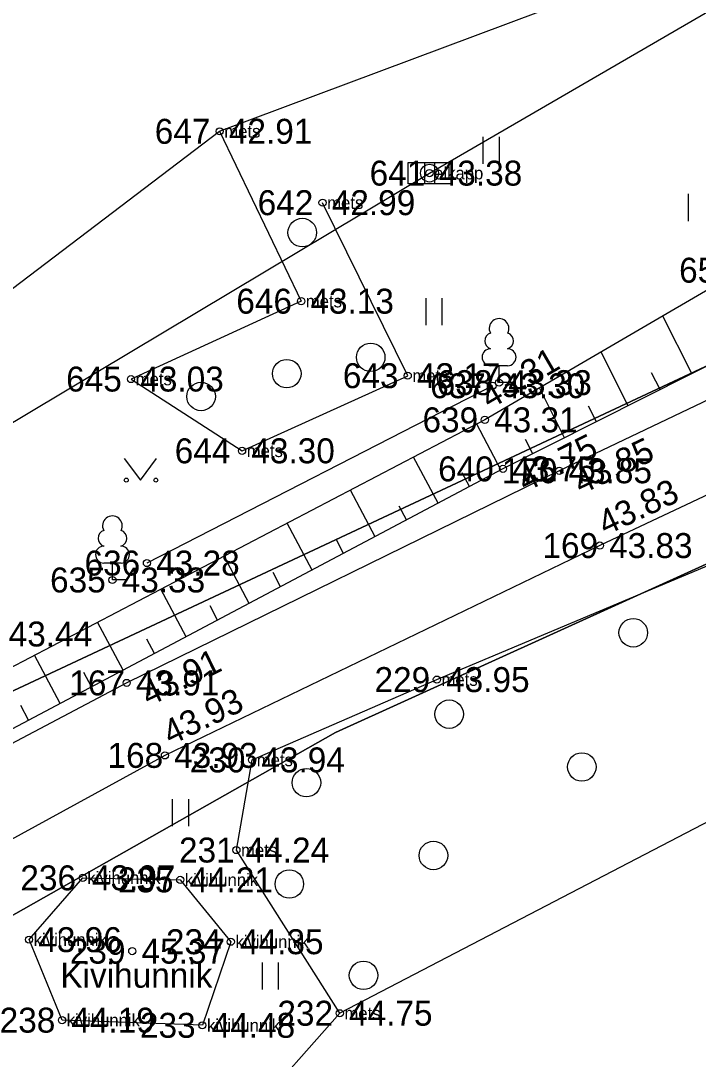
# Model space of a CAD drawing. Extents: x 505800 to 507326, y 6540058 to 6542128.
# Drawn here: x 506404.99 to 506423.99, y 6540355.67 to 6540384.81 of the extents above; entities that cross this region are included whole.
import ezdxf

# ---------------------------------------------------------------- set-up
doc = ezdxf.new("R2010")
doc.units = 0
for name, color, linetype in [('ELRAJATISMP', 7, 'Continuous'), ('HALJASTUS', 7, 'Continuous'), ('KORGUS-EH2000', 7, 'Continuous'), ('MAAMUDEL', 7, 'Continuous'), ('MOOTKORG-EH2000', 7, 'Continuous'), ('MOOTMPUNKT', 7, 'Continuous'), ('MOOTNR', 7, 'Continuous'), ('MOOTPIIR', 7, 'Continuous'), ('MPOHULIIN', 7, 'Continuous'), ('PIIR', 7, 'Continuous'), ('POST', 7, 'Continuous'), ('PUU', 7, 'Continuous'), ('RELJEEF', 7, 'Continuous'), ('TEE', 7, 'Continuous')]:
    doc.layers.add(name, color=color, linetype=linetype)

msp = doc.modelspace()

# ---------------------------------------------------------------- linework, layer by layer
at = {"layer": 'ELRAJATISMP'}
for p, q in [((506416.317, 6540380.834), (506416.317, 6540380.237)), ((506416.589, 6540380.834), (506416.589, 6540380.237))]:
    msp.add_line(p, q, dxfattribs=at)
msp.add_lwpolyline([(506415.856, 6540380.834), (506417.05, 6540380.834), (506417.05, 6540380.237), (506415.856, 6540380.237)], close=True, dxfattribs=at)
at = {"layer": 'HALJASTUS'}
for p, q in [((506417.949, 6540381.555), (506417.949, 6540380.794)), ((506418.404, 6540381.555), (506418.404, 6540380.794)), ((506423.714, 6540379.953), (506423.714, 6540379.192)), ((506416.348, 6540377.028), (506416.348, 6540376.267)), ((506416.803, 6540377.028), (506416.803, 6540376.267)), ((506418.22, 6540374.569), (506408.525, 6540369.592)), ((506407.884, 6540372.527), (506408.347, 6540371.92)), ((506408.347, 6540371.92), (506408.793, 6540372.527)), ((506409.232, 6540362.968), (506409.232, 6540362.207)), ((506409.687, 6540362.968), (506409.687, 6540362.207)), ((506411.754, 6540358.381), (506411.754, 6540357.62)), ((506412.209, 6540358.381), (506412.209, 6540357.62))]:
    msp.add_line(p, q, dxfattribs=at)
for points in [[(506413.936, 6540356.957), (506411.035, 6540361.537), (506411.476, 6540364.066), (506416.66, 6540366.321), (506428.112, 6540371.138), (506442.602, 6540377.508), (506445.225, 6540379.984), (506450.028, 6540381.664), (506456.825, 6540384.191), (506464.626, 6540386.148), (506480.51, 6540389.107), (506500.858, 6540392.966), (506504.844, 6540391.729), (506512.52, 6540393.396), (506515.37, 6540396.647), (506532.173, 6540402.941), (506544.149, 6540408.028), (506554.027, 6540411.411), (506558.081, 6540412.384), (506561.957, 6540411.866), (506565.619, 6540410.412), (506569.33, 6540407.843)], [(506410.565, 6540381.71), (506412.852, 6540376.942), (506408.079, 6540374.756), (506411.195, 6540372.742), (506415.842, 6540374.851), (506413.452, 6540379.706)], [(506410.08, 6540356.618), (506406.144, 6540356.763), (506405.218, 6540359.022), (506406.724, 6540360.757), (506409.459, 6540360.7), (506410.878, 6540358.964), (506410.08, 6540356.618)]]:
    msp.add_lwpolyline(points, dxfattribs=at)
for centre, radius in [((506412.882, 6540378.868), 0.4), ((506414.804, 6540375.366), 0.4), ((506412.448, 6540374.908), 0.4), ((506410.045, 6540374.267), 0.4), ((506407.946, 6540371.92), 0.055), ((506408.775, 6540371.92), 0.055), ((506422.169, 6540367.635), 0.4), ((506417.004, 6540365.351), 0.4), ((506420.727, 6540363.869), 0.4), ((506413, 6540363.428), 0.4), ((506416.564, 6540361.385), 0.4), ((506412.52, 6540360.584), 0.4), ((506414.602, 6540358.02), 0.4)]:
    msp.add_circle(centre, radius, dxfattribs=at)
at = {"layer": 'KORGUS-EH2000'}
for centre in [(506410.565, 6540381.71), (506416.453, 6540380.536), (506413.452, 6540379.706), (506412.852, 6540376.942), (506415.842, 6540374.851), (506408.079, 6540374.756), (506418.22, 6540374.569), (506418.406, 6540374.655), (506418.006, 6540373.612), (506411.195, 6540372.742), (506418.514, 6540372.235), (506420.092, 6540372.182), (506421.232, 6540370.083), (506408.525, 6540369.592), (506407.558, 6540369.117), (506407.957, 6540366.228), (506416.66, 6540366.321), (506409.03, 6540364.194), (506411.476, 6540364.066), (506411.035, 6540361.537), (506406.724, 6540360.757), (506409.459, 6540360.7), (506405.218, 6540359.022), (506410.878, 6540358.964), (506408.113, 6540358.7), (506406.144, 6540356.763), (506413.936, 6540356.957), (506410.08, 6540356.618)]:
    msp.add_circle(centre, 0.1, dxfattribs=at)
at = {"layer": 'MOOTMPUNKT'}
for centre in [(506410.565, 6540381.71), (506416.453, 6540380.536), (506413.452, 6540379.706), (506412.852, 6540376.942), (506415.842, 6540374.851), (506408.079, 6540374.756), (506418.22, 6540374.569), (506418.406, 6540374.655), (506418.006, 6540373.612), (506411.195, 6540372.742), (506418.514, 6540372.235), (506420.092, 6540372.182), (506421.232, 6540370.083), (506408.525, 6540369.592), (506407.558, 6540369.117), (506407.957, 6540366.228), (506416.66, 6540366.321), (506409.03, 6540364.194), (506411.476, 6540364.066), (506411.035, 6540361.537), (506406.724, 6540360.757), (506409.459, 6540360.7), (506405.218, 6540359.022), (506410.878, 6540358.964), (506408.113, 6540358.7), (506406.144, 6540356.763), (506413.936, 6540356.957), (506410.08, 6540356.618)]:
    msp.add_circle(centre, 0.1, dxfattribs=at)
at = {"layer": 'MOOTPIIR'}
for points in [[(506240.253, 6540270.959), (506245.955, 6540263.864), (506266.133, 6540270.794), (506275.983, 6540276.683), (506285.511, 6540285.657), (506298.843, 6540299.878), (506301.086, 6540304.525), (506297.722, 6540312.738), (506305.023, 6540318.445), (506309.38, 6540311.746), (506312.325, 6540315.185), (506338.029, 6540330.648), (506336.908, 6540340.183), (506347.357, 6540347.554), (506370.89, 6540361.705), (506382.389, 6540366.462), (506390.076, 6540368.866), (506400.572, 6540374.13), (506410.565, 6540381.71), (506441.143, 6540393.151), (506453.59, 6540403.335), (506461.402, 6540393.473), (506495.448, 6540402.285)], [(506495.183, 6540386.603), (506455.807, 6540378.751), (506413.936, 6540356.957), (506411.426, 6540354.112), (506402.307, 6540351.523), (506391.999, 6540341.498), (506380.901, 6540334.942), (506360.247, 6540322.568), (506353.013, 6540324.95), (506332.133, 6540309.036), (506315.598, 6540297.889), (506301.375, 6540281.904), (506292.827, 6540267.673), (506286.653, 6540264.508), (506248.469, 6540250.071)]]:
    msp.add_lwpolyline(points, dxfattribs=at)
at = {"layer": 'MPOHULIIN'}
for p, q in [((506416.453, 6540380.536), (506455.327, 6540403.116)), ((506372.493, 6540354.233), (506416.453, 6540380.536))]:
    msp.add_line(p, q, dxfattribs=at)
at = {"layer": 'PIIR'}
msp.add_lwpolyline([(506326.14, 6540370.11), (506324.04, 6540375.18), (506354.05, 6540393.57), (506395.54, 6540418.74), (506427.6, 6540438.79), (506429.21, 6540436.36), (506458.7, 6540391.28), (506340.34, 6540335.82)], close=True, dxfattribs=at)
for points in [[(506215.95, 6540254.34), (506268.55, 6540273.9), (506274.54, 6540277.85), (506304.35, 6540308.95), (506340.34, 6540335.82), (506458.7, 6540391.28), (506563.96, 6540420.02)], [(506497.85, 6540391.32), (506462.8, 6540384.69), (506453.27, 6540382.76), (506413.82, 6540364.84), (506374.55, 6540342.6), (506353.59, 6540332.53), (506318.07, 6540309.28), (506308, 6540301.95), (506281.65, 6540275.05), (506272.39, 6540267.75), (506224.13, 6540249.92)], [(506224.13, 6540249.92), (506272.39, 6540267.75), (506281.65, 6540275.05), (506308, 6540301.95), (506318.07, 6540309.28), (506353.59, 6540332.53), (506374.55, 6540342.6), (506413.82, 6540364.84), (506453.27, 6540382.76), (506462.8, 6540384.69), (506495.14, 6540337.45), (506342.85, 6540237.27), (506260.72, 6540195.9), (506215.68, 6540179.69)]]:
    msp.add_lwpolyline(points, dxfattribs=at)
at = {"layer": 'POST'}
msp.add_circle((506416.453, 6540380.536), 0.25, dxfattribs=at)
at = {"layer": 'PUU'}
for p, q in [((506418.646, 6540375.13), (506418.166, 6540375.13)), ((506418.406, 6540374.655), (506418.406, 6540375.13)), ((506418.786, 6540374.655), (506418.406, 6540374.655)), ((506407.798, 6540369.592), (506407.318, 6540369.592)), ((506407.558, 6540369.117), (506407.558, 6540369.592)), ((506407.938, 6540369.117), (506407.558, 6540369.117))]:
    msp.add_line(p, q, dxfattribs=at)
for centre, radius, start, end in [((506418.406, 6540376.175), 0.277, 332.5799, 207.4201), ((506418.236, 6540375.828), 0.233, 109.0217, 253.1415), ((506418.576, 6540375.828), 0.233, 286.8508, 70.9859), ((506418.168, 6540375.368), 0.238, 90.0016, 269.3953), ((506418.643, 6540375.368), 0.238, 270.6047, 89.9984), ((506407.558, 6540370.637), 0.277, 332.5799, 207.4201), ((506407.388, 6540370.289), 0.233, 109.0217, 253.1415), ((506407.728, 6540370.289), 0.233, 286.8508, 70.9859), ((506407.321, 6540369.829), 0.238, 90.0016, 269.3953), ((506407.796, 6540369.829), 0.238, 270.6047, 89.9984)]:
    msp.add_arc(centre, radius, start, end, dxfattribs=at)
at = {"layer": 'RELJEEF'}
for p, q in [((506423.815, 6540374.909), (506423, 6540376.525)), ((506422.03, 6540374.008), (506421.269, 6540375.515)), ((506422.923, 6540374.459), (506422.686, 6540374.927)), ((506420.244, 6540373.107), (506419.539, 6540374.506)), ((506421.137, 6540373.558), (506420.917, 6540373.994)), ((506418.459, 6540372.206), (506417.777, 6540373.492)), ((506419.351, 6540372.657), (506419.148, 6540373.06)), ((506416.692, 6540371.269), (506416.005, 6540372.565)), ((506417.575, 6540371.737), (506417.37, 6540372.125)), ((506414.925, 6540370.332), (506414.232, 6540371.639)), ((506415.808, 6540370.801), (506415.601, 6540371.191)), ((506413.157, 6540369.396), (506412.46, 6540370.712)), ((506414.041, 6540369.864), (506413.833, 6540370.258)), ((506411.39, 6540368.459), (506410.688, 6540369.785)), ((506412.274, 6540368.928), (506412.064, 6540369.324)), ((506409.623, 6540367.523), (506408.915, 6540368.859)), ((506410.507, 6540367.991), (506410.295, 6540368.39)), ((506407.856, 6540366.586), (506407.143, 6540367.932)), ((506408.739, 6540367.055), (506408.526, 6540367.457)), ((506406.089, 6540365.65), (506405.37, 6540367.005)), ((506406.972, 6540366.118), (506406.758, 6540366.523)), ((506405.205, 6540365.181), (506404.989, 6540365.59))]:
    msp.add_line(p, q, dxfattribs=at)
for points in [[(506556.207, 6540417.529), (506548.446, 6540415.756), (506537.177, 6540411.287), (506507.092, 6540401.356), (506493.818, 6540397.458), (506479.74, 6540393.488), (506463.711, 6540390.977), (506454.162, 6540389.588), (506445.961, 6540387.82), (506436.644, 6540384.929), (506428.217, 6540381.232), (506425.206, 6540377.812), (506418.006, 6540373.612), (506396.112, 6540362.165), (506387.822, 6540357.514)], [(506556.207, 6540417.529), (506549.32, 6540414.59), (506538.05, 6540410.165), (506520.494, 6540403.746), (506508.114, 6540399.97), (506494.198, 6540395.848), (506479.734, 6540392.802), (506464.199, 6540389.877), (506454.62, 6540387.729), (506446.277, 6540385.845), (506437.645, 6540382.533), (506432.878, 6540380.89), (506430.375, 6540378.218), (506418.514, 6540372.235), (506396.686, 6540360.667), (506388.239, 6540356.069)]]:
    msp.add_lwpolyline(points, dxfattribs=at)
at = {"layer": 'TEE'}
for points in [[(506478.706, 6540392.058), (506464.091, 6540389.4), (506454.678, 6540387.173), (506446.264, 6540384.451), (506435.18, 6540379.372), (506420.092, 6540372.182), (506407.957, 6540366.228), (506394.897, 6540359.329), (506383.759, 6540352.819), (506372.647, 6540346.37), (506363.224, 6540341.99), (506352.182, 6540336.393), (506347.174, 6540333.201), (506340.898, 6540329.111), (506329.323, 6540321.237)], [(506479.167, 6540389.797), (506464.651, 6540387.028), (506455.166, 6540384.708), (506447.071, 6540382.035), (506436.402, 6540377.232), (506421.232, 6540370.083), (506409.03, 6540364.194), (506396.144, 6540357.137), (506385.127, 6540350.766), (506373.749, 6540344.271), (506364.374, 6540339.718), (506353.506, 6540334.212), (506348.479, 6540331.101), (506342.338, 6540327.065), (506330.786, 6540319.25)]]:
    msp.add_lwpolyline(points, dxfattribs=at)

# ---------------------------------------------------------------- texts
at = {"layer": 'HALJASTUS'}
msp.add_text('Kivihunnik', height=0.7, dxfattribs=at).set_placement((506406.096, 6540357.674))
at = {"layer": 'KORGUS-EH2000'}
for s, p in [(' 42.91', (506410.565, 6540381.36)), (' 42.99', (506413.452, 6540379.356)), (' 43.03', (506408.079, 6540374.406)), (' 43.30', (506411.195, 6540372.392)), (' 43.95', (506416.66, 6540365.971)), (' 43.94', (506411.476, 6540363.717)), (' 44.24', (506411.035, 6540361.187)), (' 45.37', (506408.113, 6540358.35)), (' 44.19', (506406.144, 6540356.413)), (' 44.75', (506413.936, 6540356.607))]:
    msp.add_text(s, height=0.7, dxfattribs=at).set_placement(p)
for s, rotation, p in [(' 43.31', 30.255, (506417.918, 6540373.763)), (' 43.75', 26.7689, (506418.908, 6540371.454)), (' 43.85', 25.4801, (506420.469, 6540371.392)), (' 43.83', 25.2327, (506421.157, 6540370.242)), (' 43.91', 26.1323, (506408.343, 6540365.443)), (' 43.93', 25.7657, (506408.954, 6540364.351))]:
    msp.add_text(s, height=0.7, rotation=rotation, dxfattribs=at).set_placement(p)
at = {"layer": 'MAAMUDEL'}
for s, p in [(' mets', (506410.565, 6540381.535)), (' elkapp', (506416.453, 6540380.361)), (' mets', (506413.452, 6540379.531)), (' mets', (506412.852, 6540376.767)), (' mets', (506408.079, 6540374.581)), (' mets', (506415.842, 6540374.676)), (' mets', (506411.195, 6540372.567)), (' mets', (506416.66, 6540366.146)), (' mets', (506411.476, 6540363.891)), (' mets', (506411.035, 6540361.362)), (' kivihunnik', (506406.724, 6540360.582)), (' kivihunnik', (506409.459, 6540360.525)), (' kivihunnik', (506405.218, 6540358.847)), (' kivihunnik', (506410.878, 6540358.789)), (' mets', (506413.936, 6540356.782)), (' kivihunnik', (506406.144, 6540356.588)), (' kivihunnik', (506410.08, 6540356.443))]:
    msp.add_text(s, height=0.35, dxfattribs=at).set_placement(p)
at = {"layer": 'MOOTKORG-EH2000'}
for s, p in [(' 42.91', (506410.565, 6540381.36)), (' 43.38', (506416.453, 6540380.186)), (' 42.99', (506413.452, 6540379.356)), (' 43.13', (506412.852, 6540376.592)), (' 43.17', (506415.842, 6540374.501)), (' 43.03', (506408.079, 6540374.406)), (' 43.30', (506418.22, 6540374.219)), (' 43.33', (506418.406, 6540374.305)), (' 43.31', (506418.006, 6540373.262)), (' 43.30', (506411.195, 6540372.392)), (' 43.75', (506418.514, 6540371.885)), (' 43.85', (506420.092, 6540371.832)), (' 43.83', (506421.232, 6540369.733)), (' 43.28', (506408.525, 6540369.242)), (' 43.33', (506407.558, 6540368.767)), (' 43.44', (506404.386, 6540367.25)), (' 43.91', (506407.957, 6540365.878)), (' 43.95', (506416.66, 6540365.971)), (' 43.93', (506409.03, 6540363.844)), (' 43.94', (506411.476, 6540363.717)), (' 44.24', (506411.035, 6540361.187)), (' 43.97', (506406.724, 6540360.407)), (' 44.21', (506409.459, 6540360.35)), (' 43.96', (506405.218, 6540358.672)), (' 44.35', (506410.878, 6540358.614)), (' 45.37', (506408.113, 6540358.35)), (' 44.19', (506406.144, 6540356.413)), (' 44.75', (506413.936, 6540356.607)), (' 44.48', (506410.08, 6540356.268))]:
    msp.add_text(s, height=0.7, dxfattribs=at).set_placement(p)
at = {"layer": 'MOOTNR'}
for s, p in [('647 ', (506408.745, 6540381.36)), ('641 ', (506414.773, 6540380.186)), ('642 ', (506411.632, 6540379.356)), ('652 ', (506423.456, 6540377.462)), ('646 ', (506411.033, 6540376.592)), ('643 ', (506414.022, 6540374.501)), ('645 ', (506406.259, 6540374.406)), ('637 ', (506416.471, 6540374.219)), ('638 ', (506416.656, 6540374.305)), ('639 ', (506416.256, 6540373.262)), ('644 ', (506409.305, 6540372.392)), ('640 ', (506416.694, 6540371.885)), ('170 ', (506418.482, 6540371.832)), ('169 ', (506419.622, 6540369.733)), ('636 ', (506406.775, 6540369.242)), ('635 ', (506405.808, 6540368.767)), ('167 ', (506406.347, 6540365.878)), ('229 ', (506414.91, 6540365.971)), ('168 ', (506407.42, 6540363.844)), ('230 ', (506409.726, 6540363.717)), ('231 ', (506409.425, 6540361.187)), ('236 ', (506404.974, 6540360.407)), ('235 ', (506407.709, 6540360.35)), ('234 ', (506409.058, 6540358.614)), ('239 ', (506406.363, 6540358.35)), ('238 ', (506404.394, 6540356.413)), ('232 ', (506412.186, 6540356.607)), ('233 ', (506408.33, 6540356.268))]:
    msp.add_text(s, height=0.7, dxfattribs=at).set_placement(p)

doc.saveas('drawing.dxf')
